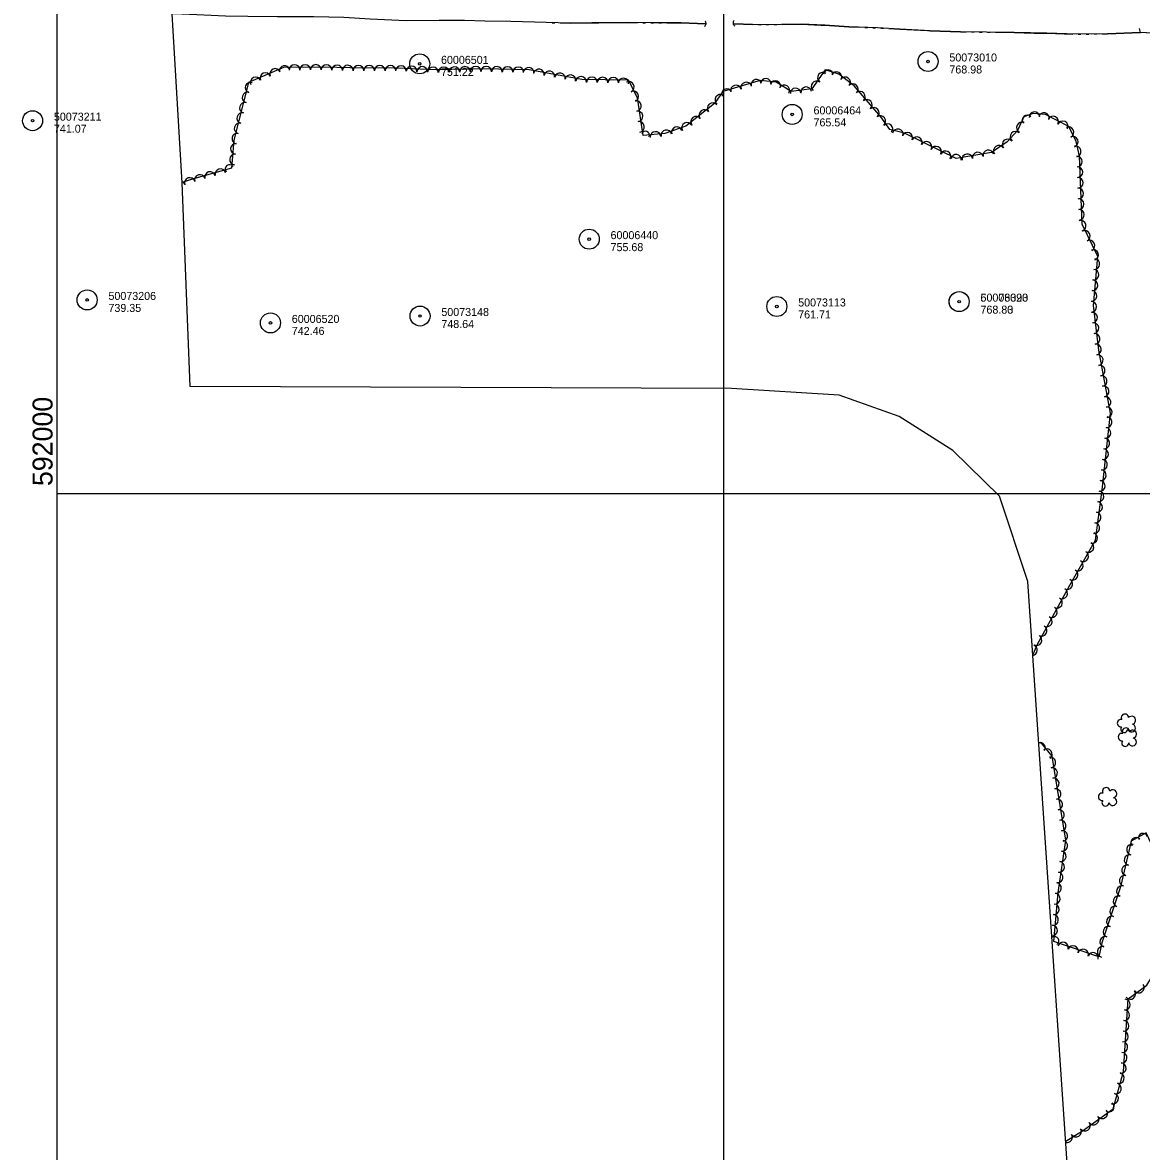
# Model space of a CAD drawing. Extents: x 591954 to 597000, y 198576 to 213500.
# Drawn here: x 591974 to 592813, y 204007 to 204853 of the extents above; entities that cross this region are included whole.
import ezdxf

# ---------------------------------------------------------------- set-up
doc = ezdxf.new("R2010")
doc.units = 0
for name, color, linetype in [('Level 10', 7, 'Continuous'), ('Level 15', 7, 'Continuous'), ('Level 18', 7, 'Continuous'), ('Level 19', 7, 'Continuous'), ('Level 4', 7, 'Continuous'), ('Level 6', 7, 'Continuous')]:
    doc.layers.add(name, color=color, linetype=linetype)

msp = doc.modelspace()

# ---------------------------------------------------------------- linework, layer by layer
at = {"layer": 'Level 10'}
for p, q in [((592000, 204500), (592000, 206000)), ((592500, 204500), (592500, 206000)), ((592000, 203500), (592000, 205000)), ((592500, 203500), (592500, 205000)), ((592000, 204500), (594000, 204500)), ((592000, 204500), (594000, 204500))]:
    msp.add_line(p, q, dxfattribs=at)
at = {"layer": 'Level 15'}
for centre, start, end in [((592509.31, 204852.86), 136.57943, 242.81899), ((592484.14, 204852.44), 300.27944, 46.519)]:
    msp.add_arc(centre, 2.5, start, end, dxfattribs=at)
at = {"layer": 'Level 18'}
for points in [[(592766.66, 204752.93), (592764.22, 204763.93), (592758.56, 204775.29), (592741.03, 204784.12), (592731.86, 204785.01), (592724.93, 204782.49), (592720.06, 204772.21), (592712.43, 204763.58), (592700.66, 204755.77), (592674.07, 204751.27), (592650.64, 204762.74), (592635.49, 204770.15), (592624.51, 204772.96), (592617.55, 204782.53), (592597.63, 204805.74), (592586.21, 204814.39), (592575.79, 204817.6), (592565.79, 204803.52), (592550.48, 204801.44), (592539.15, 204808.49), (592527.12, 204809.62), (592499.05, 204801.49), (592492.83, 204792.47), (592471.49, 204775.33), (592455.71, 204770.04), (592439.32, 204768.55), (592435.25, 204796.66), (592428.41, 204809.82), (592393.31, 204810.44), (592353.94, 204817.73), (592319.37, 204818.41), (592284.32, 204817.73), (592254.21, 204819.05), (592219.62, 204819.1), (592199.52, 204819.71), (592169.73, 204819.55), (592143.52, 204808.24), (592132.36, 204764.89), (592130.76, 204743.99), (592100.49, 204735.44), (592093.71, 204733.13)], [(592731.64, 204378.83), (592734.82, 204386.57), (592759.42, 204431.28), (592778.66, 204465.09), (592783.57, 204502.67), (592789.77, 204560.29), (592781.07, 204607.47), (592777.13, 204640.98), (592780.33, 204677.71), (592768.53, 204701.96), (592766.66, 204752.93)], [(592756.31, 204014.27), (592768.98, 204022.22), (592791.78, 204038.52), (592799.71, 204066.61), (592803.03, 204121.2), (592817.15, 204131.41), (592826.86, 204147.44), (592828.71, 204190.81), (592824.8, 204228.11), (592816.49, 204245.61), (592805.3, 204239.41), (592797.34, 204205.11), (592783.3, 204163.07), (592781.03, 204152.49), (592747.45, 204164.07), (592750.56, 204200.5), (592756.46, 204239.96), (592750.18, 204278.32), (592746.12, 204303.09), (592738.44, 204312.57), (592736.09, 204313.03)]]:
    msp.add_lwpolyline(points, dxfattribs=at)
for centre, radius, start, end in [((592170.57, 204816.81), 3.92, 10.98467, 190.96934), ((592178.03, 204817.5), 4, 0.32314, 180.30782), ((592186.02, 204817.54), 4, 0.32318, 180.30786), ((592194.01, 204817.59), 4, 0.33035, 180.31503), ((592201.94, 204817.52), 4, 358.66661, 178.65128), ((592209.91, 204817.3), 4, 358.27218, 178.25685), ((592217.92, 204817.1), 4, 358.75263, 178.73731), ((592225.95, 204817), 4, 359.92161, 179.90629), ((592233.94, 204816.99), 4, 359.91445, 179.89913), ((592241.93, 204816.98), 4, 359.91444, 179.89912), ((592249.92, 204816.96), 4, 359.91444, 179.89912), ((592257.82, 204816.79), 4, 357.58351, 177.56819), ((592148.82, 204808.24), 4, 23.34841, 203.33309), ((592156.16, 204811.41), 4, 23.35126, 203.33593), ((592163.49, 204814.58), 4, 23.34841, 203.33309), ((592265.8, 204816.45), 4, 357.48976, 177.47444), ((592273.78, 204816.09), 4, 357.49724, 177.48192), ((592281.79, 204815.79), 3.99, 358.18549, 178.17017), ((592289.88, 204815.74), 4, 1.12633, 181.111), ((592297.87, 204815.9), 4, 1.13349, 181.11817), ((592305.86, 204816.06), 4, 1.12633, 181.111), ((592313.85, 204816.21), 4, 1.12633, 181.111), ((592321.77, 204816.24), 4, 359.3192, 179.30388), ((592329.75, 204816.11), 4, 358.86749, 178.85217), ((592337.74, 204815.96), 4, 358.87466, 178.85934), ((592345.73, 204815.8), 4, 358.87466, 178.85934), ((592353.52, 204815.35), 3.98, 354.40874, 174.39342), ((592361.24, 204814.25), 4, 349.51618, 169.50086), ((592369.09, 204812.79), 4, 349.51618, 169.50086), ((592376.95, 204811.34), 4, 349.52324, 169.50791), ((592384.81, 204809.88), 4, 349.51618, 169.50086), ((592392.85, 204808.72), 3.98, 353.93049, 173.91516), ((592400.99, 204808.21), 4, 359.00371, 178.98839), ((592574.2, 204811.75), 4, 54.61502, 234.5997), ((592578.18, 204814.15), 3.51, 356.10772, 176.0924), ((592584.47, 204812.18), 3.94, 334.39631, 154.38099), ((592590.83, 204808.26), 4, 322.88678, 142.87146), ((592144.93, 204804.29), 3.84, 70.40299, 250.38767), ((592408.98, 204808.07), 4, 358.99666, 178.98134), ((592416.97, 204807.93), 4, 358.99654, 178.98122), ((592424.67, 204807.62), 3.85, 355.181, 175.16568), ((592428.66, 204804.79), 4, 297.46734, 117.45201), ((592509.02, 204802.2), 4, 16.16777, 196.15245), ((592516.7, 204804.42), 4, 16.17466, 196.15933), ((592524.33, 204806.55), 3.98, 14.77578, 194.76046), ((592531.43, 204807.12), 4, 354.64313, 174.62781), ((592538.55, 204805.58), 3.89, 339.91884, 159.90352), ((592545.19, 204802.27), 4, 328.0798, 148.06448), ((592553.7, 204800.12), 3.9, 3.38879, 183.37347), ((592561.71, 204800.85), 4, 7.74021, 187.72488), ((592569.42, 204805.33), 3.94, 52.50298, 232.48766), ((592596.63, 204803.24), 3.97, 315.16059, 135.14526), ((592142.78, 204796.95), 4, 75.56447, 255.54914), ((592432.03, 204797.76), 3.96, 293.33649, 113.32117), ((592497.25, 204795.19), 4, 55.43267, 235.41735), ((592502.1, 204799.6), 3.81, 26.74083, 206.72551), ((592601.93, 204797.52), 4, 310.64318, 130.62785), ((592607.13, 204791.46), 4, 310.64784, 130.63252), ((592140.78, 204789.21), 4, 75.55573, 255.54041), ((592434, 204790.69), 4, 278.25336, 98.23804), ((592435.14, 204782.78), 4, 278.25336, 98.23804), ((592485.39, 204783.8), 4, 38.77386, 218.75854), ((592491.57, 204788.92), 3.98, 40.33107, 220.31575), ((592612.34, 204785.39), 4, 310.64318, 130.62785), ((592138.79, 204781.48), 4, 75.56447, 255.54914), ((592436.29, 204774.87), 4, 278.25336, 98.23804), ((592479.16, 204778.8), 4, 38.77945, 218.76413), ((592617.25, 204779.28), 3.99, 306.91917, 126.90385), ((592723.4, 204774.53), 3.99, 63.76395, 243.74863), ((592727.34, 204780.02), 3.7, 41.39269, 221.37736), ((592732.89, 204782.19), 3.9, 4.68408, 184.66876), ((592739.87, 204781.55), 3.93, 345.07108, 165.05576), ((592746.83, 204778.86), 4, 333.28548, 153.27016), ((592753.96, 204775.26), 4, 333.28548, 153.27016), ((592135.02, 204766.07), 3.98, 78.47764, 258.46232), ((592136.8, 204773.74), 4, 75.55752, 255.5422), ((592441.19, 204768.64), 3.03, 338.87253, 158.85721), ((592448.76, 204767.31), 4, 5.19884, 185.18352), ((592456.89, 204768.64), 3.97, 13.24033, 193.22501), ((592464.73, 204770.86), 4, 18.5333, 198.51798), ((592472.29, 204774.22), 3.93, 29.06226, 209.04694), ((592622.85, 204773.34), 3.79, 318.52731, 138.51199), ((592630.35, 204769.3), 4, 345.65316, 165.63784), ((592637.48, 204766.76), 3.99, 335.08754, 155.07221), ((592718.68, 204767.49), 4, 48.52359, 228.50826), ((592758.42, 204770.84), 3.99, 296.91663, 116.9013), ((592133.96, 204758.44), 4, 85.64415, 265.62883), ((592644.64, 204763.34), 4, 333.96533, 153.95001), ((592651.82, 204759.83), 4, 333.91723, 153.90191), ((592712.72, 204761.77), 3.96, 39.31436, 219.29904), ((592761.56, 204763.78), 3.97, 290.93732, 110.922), ((592133.35, 204750.48), 4, 85.63646, 265.62113), ((592659, 204756.32), 4, 333.91723, 153.90191), ((592666.17, 204752.8), 4, 333.91079, 153.89547), ((592674.21, 204750.47), 3.8, 352.81912, 172.8038), ((592682.52, 204750.58), 4, 9.62559, 189.61027), ((592690.39, 204751.91), 4, 9.61852, 189.6032), ((592698.3, 204753.53), 3.95, 13.22078, 193.20545), ((592706.16, 204756.91), 4, 33.57443, 213.55911), ((592763.74, 204756.46), 4, 282.51858, 102.50326), ((592764.74, 204748.9), 3.95, 272.10353, 92.08821), ((592129.38, 204743.21), 3.36, 37.66666, 217.65133), ((592765.01, 204740.96), 4, 272.10886, 92.09353), ((592099.42, 204732.81), 3.99, 18.00261, 197.98729), ((592106.98, 204735.1), 4, 15.78166, 195.76634), ((592114.67, 204737.27), 4, 15.77971, 195.76439), ((592122.36, 204739.45), 4, 15.77971, 195.76439), ((592765.3, 204732.98), 4, 272.10859, 92.09327), ((592091.87, 204730.29), 4, 18.83715, 63.276), ((592765.59, 204724.99), 4, 272.10169, 92.08637), ((592765.89, 204717), 4, 272.10859, 92.09327), ((592766.18, 204709.02), 4, 272.10886, 92.09353), ((592767.57, 204700.76), 3.91, 286.60664, 106.59132), ((592770.52, 204693.09), 4, 295.96041, 115.94509), ((592774.02, 204685.9), 4, 295.9571, 115.94178), ((592776.98, 204678.88), 3.89, 288.915, 108.89968), ((592777.74, 204672.06), 4, 265.02612, 85.0108), ((592776.35, 204656.14), 4, 265.0255, 85.01018), ((592777.05, 204664.1), 4, 265.02612, 85.0108), ((592775.66, 204648.18), 4, 265.02612, 85.0108), ((592775.47, 204639.96), 3.98, 272.27754, 92.26222), ((592776.1, 204631.85), 4, 276.71917, 96.70385), ((592777.03, 204623.92), 4, 276.71917, 96.70385), ((592777.97, 204615.98), 4, 276.71917, 96.70385), ((592779.01, 204608), 3.99, 278.19761, 98.18229), ((592780.32, 204600.04), 4, 280.44718, 100.43186), ((592781.77, 204592.18), 4, 280.45293, 100.43761), ((592783.21, 204584.32), 4, 280.44718, 100.43186), ((592784.66, 204576.46), 4, 280.44588, 100.43056), ((592786.11, 204568.6), 4, 280.44588, 100.43056), ((592787.1, 204560.96), 3.96, 273.92868, 93.91336), ((592786.93, 204553.41), 4, 263.87332, 83.85799), ((592785.22, 204537.52), 4, 263.86619, 83.85087), ((592786.07, 204545.46), 4, 263.86619, 83.85087), ((592784.36, 204529.57), 4, 263.87408, 83.85876), ((592783.51, 204521.62), 4, 263.86619, 83.85087), ((592782.65, 204513.68), 4, 263.87332, 83.85799), ((592781.79, 204505.74), 4, 263.67855, 83.66323), ((592780.83, 204497.85), 4, 262.56605, 82.55073), ((592779.8, 204489.92), 4, 262.55987, 82.54455), ((592778.76, 204482), 4, 262.55894, 82.54362), ((592777.72, 204474.07), 4, 262.55987, 82.54455), ((592776.21, 204466.65), 3.92, 253.68321, 73.66789), ((592773.28, 204459.87), 4, 240.36949, 60.35417), ((592765.38, 204445.98), 4, 240.36949, 60.35417), ((592769.33, 204452.92), 4, 240.36326, 60.34794), ((592761.42, 204439.03), 4, 240.36326, 60.34794), ((592757.49, 204432.05), 4, 240.80613, 60.7908), ((592753.61, 204425.05), 4, 241.19121, 61.17589), ((592745.9, 204411.05), 4, 241.19467, 61.17935), ((592749.76, 204418.05), 4, 241.18493, 61.16961), ((592742.05, 204404.05), 4, 241.18493, 61.16961), ((592738.2, 204397.04), 4, 241.19121, 61.17589), ((592734.39, 204389.98), 3.99, 242.1365, 62.12118), ((592730.92, 204382.57), 4, 280.63428, 67.65977), ((592797.71, 204327.79), 2.78, 78.07156, 279.08261), ((592800.71, 204331.86), 2.78, 1.39455, 209.16754), ((592805.75, 204330.01), 2.97, 278.42366, 139.65754), ((592800.17, 204323.39), 2.61, 140.77971, 358.71232), ((592801.44, 204321.46), 2.78, 1.39455, 209.16754), ((592805.64, 204324.15), 2.97, 196.07448, 79.04774), ((592806.48, 204319.6), 2.97, 278.42366, 139.65754), ((592737.18, 204309.44), 3.77, 325.29181, 106.74758), ((592798.44, 204317.39), 2.78, 78.07156, 279.08261), ((592800.9, 204312.99), 2.61, 140.77971, 358.71232), ((592806.37, 204313.75), 2.97, 196.07448, 79.04774), ((592742.14, 204304.51), 3.97, 307.27056, 127.25524), ((592744.78, 204298.33), 4, 279.31795, 99.30263), ((592746.07, 204290.44), 4, 279.31088, 99.29555), ((592747.36, 204282.55), 4, 279.31088, 99.29555), ((592786.59, 204276.72), 2.78, 1.39455, 209.16754), ((592748.66, 204274.67), 4, 279.30496, 99.28964), ((592749.95, 204266.78), 4, 279.31088, 99.29555), ((592783.59, 204272.64), 2.78, 78.07156, 279.08261), ((592791.53, 204269.01), 2.97, 196.07448, 79.04774), ((592791.64, 204274.86), 2.97, 278.42366, 139.65754), ((592751.24, 204258.89), 4, 279.31088, 99.29555), ((592786.06, 204268.24), 2.61, 140.77971, 358.71232), ((592752.53, 204251.01), 4, 279.31088, 99.29555), ((592753.75, 204243.16), 3.99, 278.30955, 98.29423), ((592814.33, 204241.74), 3.45, 19.82496, 199.80963), ((592753.73, 204235.87), 4, 261.50242, 81.4871), ((592805.96, 204233.01), 4, 76.93996, 256.92464), ((592808.93, 204238.35), 3.73, 40.98275, 220.96743), ((592752.55, 204227.97), 4, 261.50242, 81.4871), ((592804.16, 204225.23), 4, 76.94695, 256.93162), ((592751.37, 204220.06), 4, 261.50951, 81.49419), ((592802.35, 204217.44), 4, 76.93996, 256.92464), ((592750.19, 204212.16), 4, 261.50242, 81.4871), ((592800.54, 204209.66), 4, 76.94695, 256.93162), ((592749.02, 204204.24), 4, 261.74067, 81.72535), ((592798.38, 204201.8), 3.99, 72.31901, 252.30369), ((592748.09, 204196.19), 4, 265.11959, 85.10427), ((592795.89, 204194.17), 4, 71.54324, 251.52792), ((592747.41, 204188.22), 4, 265.11959, 85.10427), ((592793.36, 204186.59), 4, 71.53871, 251.52339), ((592746.73, 204180.26), 4, 265.11898, 85.10366), ((592790.83, 204179.01), 4, 71.53644, 251.52112), ((592746.05, 204172.3), 4, 267.68582, 85.10427), ((592788.3, 204171.43), 4, 71.54324, 251.52792), ((592748.07, 204164.59), 3.15, 302.12962, 122.11429), ((592754.24, 204159.52), 4, 340.97878, 160.96346), ((592761.8, 204156.91), 4, 340.98323, 160.9679), ((592785.92, 204163.88), 3.99, 73.50712, 253.4918), ((592769.35, 204154.31), 4, 340.97645, 160.96113), ((592776.9, 204152), 3.8, 343.63471, 163.61939), ((592783.99, 204156.31), 4, 77.89488, 257.87956), ((592804.76, 204124.73), 3.91, 218.75794, 38.74261), ((592811.11, 204129.62), 4, 215.85952, 35.8442), ((592800.67, 204116.83), 4, 266.52881, 86.51349), ((592800.18, 204108.85), 4, 266.53553, 86.52021), ((592799.7, 204100.87), 4, 266.52837, 86.51305), ((592799.21, 204092.9), 4, 266.52837, 86.51305), ((592798.73, 204084.92), 4, 266.52837, 86.51305), ((592798.24, 204076.94), 4, 266.53596, 86.52064), ((592797.59, 204069.1), 3.98, 263.8193, 83.80398), ((592796.13, 204061.64), 4, 254.23951, 74.22418), ((592793.96, 204053.95), 4, 254.23756, 74.22223), ((592788.84, 204040.07), 3.78, 232.15264, 52.13732), ((592791.79, 204046.25), 4, 254.23756, 74.22223), ((592783.62, 204035.26), 4, 215.57118, 35.55585), ((592770.61, 204025.98), 4, 215.35447, 35.33914), ((592777.11, 204030.61), 4, 215.57701, 35.56168), ((592757.3, 204017.36), 4, 256.52354, 32.09348), ((592764.07, 204021.61), 4, 212.1088, 32.09348)]:
    msp.add_arc(centre, radius, start, end, dxfattribs=at)
at = {"layer": 'Level 19'}
for points in [[(592486.17, 204852.17), (592467.93, 204852.86), (592446.62, 204852.85), (592427.44, 204853.1), (592400.84, 204852.85), (592384.81, 204852.76), (592366.75, 204853.14), (592340.17, 204853.86), (592320.59, 204854.27), (592305.51, 204854.72), (592286.4, 204854.78), (592261.67, 204854.35), (592234.71, 204855.59), (592215.07, 204857.01), (592192.45, 204857.32), (592164.87, 204857.54), (592142.88, 204857.72), (592126.11, 204857.91), (592104.77, 204858.82), (592087.89, 204859.58), (592086.27, 204859.59)], [(592371.19, 204853.05), (592373.19, 204853.01)], [(592377.19, 204852.92), (592384.81, 204852.76), (592400.84, 204852.85), (592406.18, 204852.9)], [(592406.18, 204852.9), (592427.44, 204853.1), (592435.18, 204853)], [(592439.18, 204852.95), (592441.18, 204852.92)], [(592445.18, 204852.87), (592446.62, 204852.85), (592447.18, 204852.85)], [(592451.18, 204852.85), (592453.18, 204852.85)], [(592457.18, 204852.86), (592467.93, 204852.86), (592486.17, 204852.17)], [(592812.49, 204845.61), (592787.63, 204844.7), (592764.57, 204844.46), (592742.22, 204845.08), (592717.56, 204845.6), (592696.89, 204845.97), (592677.3, 204846.21), (592654.68, 204847.02), (592632, 204848.14), (592615.2, 204849.2), (592593.61, 204849.81), (592575.72, 204851.07), (592557.91, 204851.95), (592528.51, 204851.51), (592507.43, 204852.13)], [(592507.43, 204852.13), (592521.68, 204851.71)], [(592507.43, 204852.13), (592521.68, 204851.71)], [(592525.68, 204851.6), (592527.68, 204851.54)], [(592525.68, 204851.6), (592527.68, 204851.54)], [(592531.68, 204851.56), (592533.68, 204851.59)], [(592531.68, 204851.56), (592533.68, 204851.59)], [(592537.68, 204851.65), (592539.68, 204851.68)], [(592537.68, 204851.65), (592539.68, 204851.68)], [(592543.68, 204851.74), (592557.91, 204851.95), (592572.66, 204851.22)], [(592543.68, 204851.74), (592557.91, 204851.95), (592572.66, 204851.22)], [(592572.66, 204851.22), (592575.72, 204851.07), (592593.61, 204849.81), (592601.6, 204849.58)], [(592572.66, 204851.22), (592575.72, 204851.07), (592593.61, 204849.81), (592601.6, 204849.58)], [(592605.6, 204849.47), (592607.6, 204849.42)], [(592605.6, 204849.47), (592607.6, 204849.42)], [(592611.6, 204849.3), (592613.6, 204849.25)], [(592611.6, 204849.3), (592613.6, 204849.25)], [(592617.59, 204849.05), (592619.59, 204848.93)], [(592617.59, 204849.05), (592619.59, 204848.93)], [(592623.58, 204848.68), (592632, 204848.14), (592652.54, 204847.13)], [(592623.58, 204848.68), (592632, 204848.14), (592652.54, 204847.13)], [(592652.54, 204847.13), (592654.68, 204847.02), (592677.3, 204846.21), (592681.52, 204846.16)], [(592652.54, 204847.13), (592654.68, 204847.02), (592677.3, 204846.21), (592681.52, 204846.16)], [(592685.52, 204846.11), (592687.52, 204846.09)], [(592685.52, 204846.11), (592687.52, 204846.09)], [(592691.52, 204846.04), (592693.52, 204846.01)], [(592691.52, 204846.04), (592693.52, 204846.01)], [(592697.52, 204845.96), (592699.52, 204845.93)], [(592812.49, 204845.61), (592811.61, 204848.58)], [(592812.49, 204845.61), (592811.61, 204848.58)], [(592703.52, 204845.85), (592717.56, 204845.6), (592732.52, 204845.29)], [(592703.52, 204845.85), (592717.56, 204845.6), (592732.52, 204845.29)], [(592732.52, 204845.29), (592742.22, 204845.08), (592761.51, 204844.54)], [(592732.52, 204845.29), (592742.22, 204845.08), (592761.51, 204844.54)], [(592765.51, 204844.47), (592767.51, 204844.49)], [(592771.51, 204844.53), (592773.51, 204844.55)], [(592777.5, 204844.59), (592779.5, 204844.61)], [(592777.5, 204844.59), (592779.5, 204844.61)], [(592783.5, 204844.66), (592787.63, 204844.7), (592812.49, 204845.61)], [(592783.5, 204844.66), (592787.63, 204844.7), (592812.49, 204845.61)], [(592896.91, 204843.66), (592873.98, 204843.71), (592851.66, 204844.44), (592829.52, 204844.8), (592812.49, 204845.61)], [(592816.94, 204845.4), (592812.49, 204845.61)]]:
    msp.add_lwpolyline(points, dxfattribs=at)
at = {"layer": 'Level 4'}
for points in [[(592093.72, 204732.92), (592069.11, 205151.36), (592455.29, 205161.69), (592724.44, 205643.32)], [(592770.19, 203809.11), (592727.9, 204434.13), (592706.56, 204498.06), (592671.72, 204532.3), (592631.44, 204557.77), (592586.5, 204573.72), (592505.54, 204578.83), (592099.8, 204580.23), (592093.72, 204732.92)]]:
    msp.add_lwpolyline(points, dxfattribs=at)
at = {"layer": 'Level 6'}
for centre, radius in [((592271.84, 204822.16), 7.5), ((592271.84, 204822.16), 7.5), ((592271.84, 204822.16), 7.5), ((592653.04, 204823.95), 7.5), ((592653.04, 204823.95), 7.5), ((592653.04, 204823.95), 7.5), ((592271.84, 204822.16), 0.96), ((592271.84, 204822.16), 0.96), ((592271.84, 204822.16), 0.96), ((592653.04, 204823.95), 0.96), ((592653.04, 204823.95), 0.96), ((592653.04, 204823.95), 0.96), ((591981.56, 204779.55), 7.5), ((591981.56, 204779.55), 7.5), ((591981.56, 204779.55), 7.5), ((592551.16, 204784.27), 7.5), ((592551.16, 204784.27), 7.5), ((592551.16, 204784.27), 7.5), ((591981.56, 204779.55), 0.96), ((591981.56, 204779.55), 0.96), ((591981.56, 204779.55), 0.96), ((592551.16, 204784.27), 0.96), ((592551.16, 204784.27), 0.96), ((592551.16, 204784.27), 0.96), ((592398.97, 204690.73), 7.5), ((592398.97, 204690.73), 7.5), ((592398.97, 204690.73), 7.5), ((592398.97, 204690.73), 0.96), ((592398.97, 204690.73), 0.96), ((592398.97, 204690.73), 0.96), ((592022.46, 204645.15), 7.5), ((592022.46, 204645.15), 7.5), ((592022.46, 204645.15), 7.5), ((592676.36, 204643.87), 7.5), ((592676.36, 204643.87), 7.5), ((592676.36, 204643.87), 7.5), ((592676.38, 204643.88), 7.5), ((592676.38, 204643.88), 7.5), ((592676.38, 204643.88), 7.5), ((592022.46, 204645.15), 0.96), ((592022.46, 204645.15), 0.96), ((592022.46, 204645.15), 0.96), ((592539.67, 204640.25), 7.5), ((592539.67, 204640.25), 7.5), ((592539.67, 204640.25), 7.5), ((592676.36, 204643.87), 0.96), ((592676.36, 204643.87), 0.96), ((592676.36, 204643.87), 0.96), ((592676.38, 204643.88), 0.96), ((592676.38, 204643.88), 0.96), ((592676.38, 204643.88), 0.96), ((592159.94, 204627.91), 7.5), ((592159.94, 204627.91), 7.5), ((592159.94, 204627.91), 7.5), ((592272.1, 204633.1), 7.5), ((592272.1, 204633.1), 7.5), ((592272.1, 204633.1), 7.5), ((592539.67, 204640.25), 0.96), ((592539.67, 204640.25), 0.96), ((592539.67, 204640.25), 0.96), ((592159.94, 204627.91), 0.96), ((592159.94, 204627.91), 0.96), ((592159.94, 204627.91), 0.96), ((592272.1, 204633.1), 0.96), ((592272.1, 204633.1), 0.96), ((592272.1, 204633.1), 0.96)]:
    msp.add_circle(centre, radius, dxfattribs=at)

# ---------------------------------------------------------------- texts
at = {"layer": 'Level 10'}
msp.add_text(' 592000 ', height=15, rotation=90, dxfattribs=at).set_placement((591996.55, 204500))
at = {"layer": 'Level 6'}
for s, p in [('50073010', (592669.05, 204823.95)), ('50073010', (592669.05, 204823.95)), ('50073010', (592669.05, 204823.95)), ('60006501', (592287.84, 204822.16)), ('60006501', (592287.84, 204822.16)), ('60006501', (592287.84, 204822.16)), ('768.98', (592669.05, 204814.95)), ('768.98', (592669.05, 204814.95)), ('768.98', (592669.05, 204814.95)), ('751.22', (592287.84, 204813.16)), ('751.22', (592287.84, 204813.16)), ('751.22', (592287.84, 204813.16)), ('60006464', (592567.16, 204784.27)), ('60006464', (592567.16, 204784.27)), ('60006464', (592567.16, 204784.27)), ('50073211', (591997.56, 204779.55)), ('50073211', (591997.56, 204779.55)), ('50073211', (591997.56, 204779.55)), ('765.54', (592567.16, 204775.27)), ('765.54', (592567.16, 204775.27)), ('765.54', (592567.16, 204775.27)), ('741.07', (591997.56, 204770.55)), ('741.07', (591997.56, 204770.55)), ('741.07', (591997.56, 204770.55)), ('60006440', (592414.97, 204690.73)), ('60006440', (592414.97, 204690.73)), ('60006440', (592414.97, 204690.73)), ('755.68', (592414.97, 204681.73)), ('755.68', (592414.97, 204681.73)), ('755.68', (592414.97, 204681.73)), ('50073206', (592038.46, 204645.15)), ('50073206', (592038.46, 204645.15)), ('50073206', (592038.46, 204645.15)), ('50073113', (592555.67, 204640.25)), ('50073113', (592555.67, 204640.25)), ('50073113', (592555.67, 204640.25)), ('50073023', (592692.36, 204643.87)), ('50073023', (592692.36, 204643.87)), ('50073023', (592692.36, 204643.87)), ('60006390', (592692.39, 204643.88)), ('60006390', (592692.39, 204643.88)), ('60006390', (592692.39, 204643.88)), ('739.35', (592038.46, 204636.15)), ('739.35', (592038.46, 204636.15)), ('739.35', (592038.46, 204636.15)), ('50073148', (592288.1, 204633.1)), ('50073148', (592288.1, 204633.1)), ('50073148', (592288.1, 204633.1)), ('761.71', (592555.67, 204631.25)), ('761.71', (592555.67, 204631.25)), ('761.71', (592555.67, 204631.25)), ('768.80', (592692.36, 204634.87)), ('768.80', (592692.36, 204634.87)), ('768.80', (592692.36, 204634.87)), ('768.83', (592692.39, 204634.88)), ('768.83', (592692.39, 204634.88)), ('768.83', (592692.39, 204634.88)), ('60006520', (592175.94, 204627.91)), ('60006520', (592175.94, 204627.91)), ('60006520', (592175.94, 204627.91)), ('748.64', (592288.1, 204624.1)), ('748.64', (592288.1, 204624.1)), ('748.64', (592288.1, 204624.1)), ('742.46', (592175.94, 204618.91)), ('742.46', (592175.94, 204618.91)), ('742.46', (592175.94, 204618.91))]:
    msp.add_text(s, height=6, dxfattribs=at).set_placement(p)

doc.saveas('drawing.dxf')
